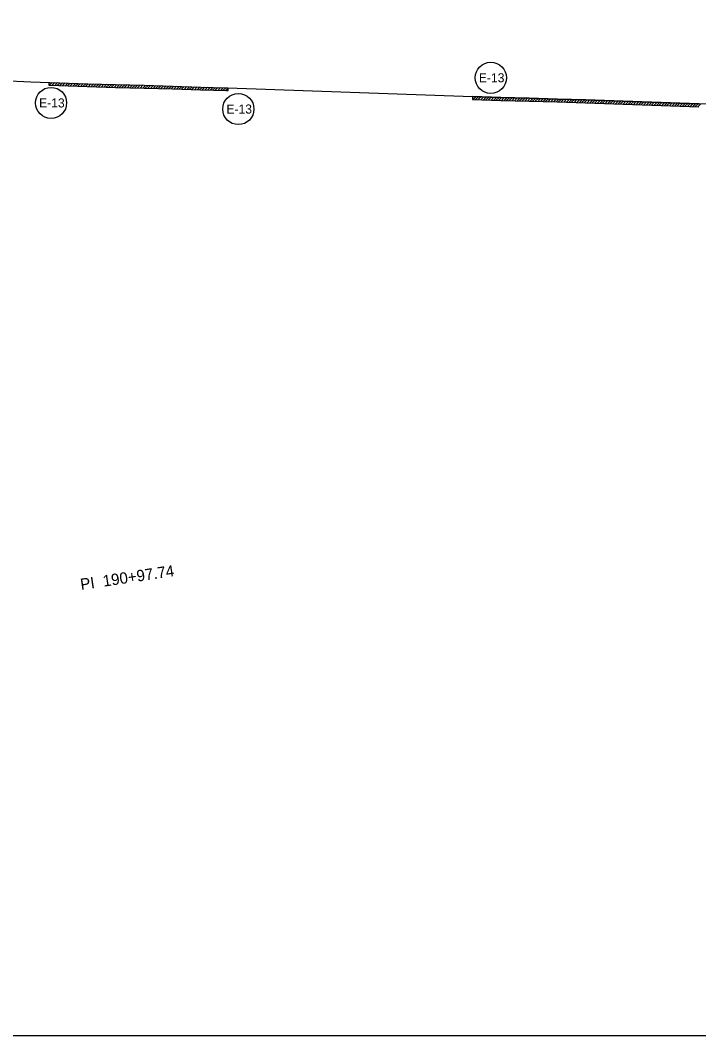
# Model space of a CAD drawing. Extents: x 976877 to 983987, y 1525984 to 1526526.
# Drawn here: x 977846 to 978205, y 1525984 to 1526522 of the extents above; entities that cross this region are included whole.
import ezdxf

# ---------------------------------------------------------------- set-up
doc = ezdxf.new("R2010")
doc.units = 0
for name, color, linetype in [('R_Erosion', 7, 'Continuous'), ('R_Horz Alg Annot', 7, 'Continuous'), ('R_No Plot', 7, 'Continuous')]:
    doc.layers.add(name, color=color, linetype=linetype)

msp = doc.modelspace()

# ---------------------------------------------------------------- linework, layer by layer
at = {"layer": 'R_Erosion'}
for p, q in [((977860.91, 1526489.41), (977860.86, 1526487.91)), ((977860.89, 1526488.9), (977861.38, 1526489.39)), ((977860.91, 1526489.41), (977866.34, 1526489.23)), ((977861.3, 1526487.89), (977862.75, 1526489.35)), ((977862.67, 1526487.85), (977864.12, 1526489.3)), ((977864.04, 1526487.81), (977865.49, 1526489.26)), ((977865.41, 1526487.76), (977866.86, 1526489.21)), ((977866.77, 1526487.71), (977868.22, 1526489.16)), ((977868.13, 1526487.66), (977869.58, 1526489.1)), ((977869.49, 1526487.6), (977870.94, 1526489.05)), ((977870.85, 1526487.55), (977872.3, 1526488.99)), ((977872.21, 1526487.5), (977873.66, 1526488.94)), ((977873.57, 1526487.44), (977875.02, 1526488.88)), ((977874.93, 1526487.39), (977876.38, 1526488.83)), ((977876.29, 1526487.33), (977877.74, 1526488.78)), ((977877.65, 1526487.28), (977879.1, 1526488.72)), ((977879.01, 1526487.22), (977880.46, 1526488.67)), ((977880.37, 1526487.17), (977881.82, 1526488.62)), ((977881.74, 1526487.12), (977883.2, 1526488.58)), ((977883.12, 1526487.09), (977884.58, 1526488.55)), ((977884.5, 1526487.05), (977885.96, 1526488.51)), ((977885.87, 1526487.01), (977887.34, 1526488.48)), ((977887.25, 1526486.98), (977888.71, 1526488.44)), ((977888.63, 1526486.94), (977890.09, 1526488.41)), ((977890.01, 1526486.91), (977891.47, 1526488.37)), ((977891.39, 1526486.87), (977892.85, 1526488.33)), ((977892.77, 1526486.84), (977894.23, 1526488.3)), ((977894.14, 1526486.8), (977895.61, 1526488.26)), ((977895.52, 1526486.76), (977896.99, 1526488.23)), ((977896.33, 1526488.24), (977911.45, 1526487.85)), ((977896.9, 1526486.73), (977898.36, 1526488.19)), ((977898.28, 1526486.69), (977899.74, 1526488.15)), ((977899.66, 1526486.66), (977901.12, 1526488.12)), ((977901.04, 1526486.62), (977902.5, 1526488.08)), ((977902.41, 1526486.58), (977903.88, 1526488.05)), ((977903.79, 1526486.55), (977905.25, 1526488.01)), ((977905.17, 1526486.51), (977906.63, 1526487.97)), ((977906.55, 1526486.48), (977908.01, 1526487.94)), ((977907.93, 1526486.44), (977909.39, 1526487.9)), ((977909.31, 1526486.4), (977910.77, 1526487.87)), ((977910.68, 1526486.37), (977912.14, 1526487.83)), ((977911.45, 1526487.85), (977926.44, 1526487.39)), ((977912.06, 1526486.33), (977913.51, 1526487.78)), ((977913.43, 1526486.29), (977914.89, 1526487.74)), ((977914.8, 1526486.24), (977916.26, 1526487.7)), ((977916.17, 1526486.2), (977917.63, 1526487.66)), ((977917.55, 1526486.16), (977919, 1526487.62)), ((977918.92, 1526486.12), (977920.37, 1526487.57)), ((977920.29, 1526486.08), (977921.75, 1526487.53)), ((977921.66, 1526486.03), (977923.12, 1526487.49)), ((977923.03, 1526485.99), (977924.49, 1526487.45)), ((977924.41, 1526485.95), (977925.86, 1526487.4)), ((977925.78, 1526485.91), (977927.23, 1526487.36)), ((977927.15, 1526485.86), (977928.61, 1526487.32)), ((977928.52, 1526485.82), (977929.98, 1526487.28)), ((977929.89, 1526485.78), (977931.35, 1526487.23)), ((977931.26, 1526485.74), (977932.72, 1526487.19)), ((977932.64, 1526485.69), (977934.09, 1526487.15)), ((977934.01, 1526485.65), (977935.46, 1526487.11)), ((977935.38, 1526485.61), (977936.83, 1526487.06)), ((977936.75, 1526485.56), (977938.21, 1526487.02)), ((977938.12, 1526485.52), (977939.58, 1526486.98)), ((977939.49, 1526485.48), (977940.95, 1526486.93)), ((977940.86, 1526485.44), (977942.32, 1526486.89)), ((977942.24, 1526485.39), (977943.69, 1526486.85)), ((977943.61, 1526485.35), (977945.07, 1526486.81)), ((977944.98, 1526485.31), (977946.44, 1526486.77)), ((977946.36, 1526485.27), (977947.81, 1526486.73)), ((977947.73, 1526485.23), (977949.19, 1526486.69)), ((977949.1, 1526485.19), (977950.56, 1526486.65)), ((977950.48, 1526485.15), (977951.93, 1526486.6)), ((977951.85, 1526485.11), (977953.31, 1526486.56)), ((977953.22, 1526485.07), (977954.68, 1526486.52)), ((977954.59, 1526485.02), (977955.77, 1526486.2)), ((977955.14, 1526486.51), (977955.78, 1526486.49)), ((977955.78, 1526486.49), (977955.74, 1526484.99)), ((978085.55, 1526481.83), (978085.5, 1526480.33)), ((978085.5, 1526480.33), (978100.5, 1526479.86)), ((978085.5, 1526480.33), (978100.5, 1526479.86)), ((978085.54, 1526481.49), (978085.87, 1526481.82)), ((978085.79, 1526480.32), (978087.24, 1526481.78)), ((978087.16, 1526480.28), (978088.61, 1526481.74)), ((978088.53, 1526480.24), (978089.98, 1526481.69)), ((978089.9, 1526480.19), (978091.35, 1526481.65)), ((978091.27, 1526480.15), (978092.72, 1526481.61)), ((978092.64, 1526480.11), (978094.09, 1526481.56)), ((978094.01, 1526480.06), (978095.46, 1526481.52)), ((978095.38, 1526480.02), (978096.84, 1526481.48)), ((978096.75, 1526479.98), (978098.21, 1526481.43)), ((978098.12, 1526479.93), (978099.58, 1526481.39)), ((978099.49, 1526479.89), (978100.95, 1526481.35)), ((978100.87, 1526479.85), (978102.33, 1526481.31)), ((978102.24, 1526479.81), (978103.71, 1526481.28)), ((978103.62, 1526479.78), (978105.08, 1526481.24)), ((978105, 1526479.74), (978106.46, 1526481.2)), ((978106.38, 1526479.7), (978107.84, 1526481.17)), ((978107.76, 1526479.67), (978109.22, 1526481.13)), ((978109.13, 1526479.63), (978110.6, 1526481.09)), ((978110.51, 1526479.6), (978111.97, 1526481.06)), ((978111.89, 1526479.56), (978113.35, 1526481.02)), ((978113.27, 1526479.52), (978114.73, 1526480.99)), ((978114.65, 1526479.49), (978116.11, 1526480.95)), ((978130.52, 1526480.56), (978115.54, 1526480.96)), ((978116.02, 1526479.45), (978117.49, 1526480.91)), ((978117.4, 1526479.41), (978118.86, 1526480.87)), ((978118.78, 1526479.38), (978120.24, 1526480.84)), ((978120.15, 1526479.34), (978121.62, 1526480.8)), ((978121.53, 1526479.3), (978122.99, 1526480.76)), ((978122.91, 1526479.26), (978124.37, 1526480.72)), ((978124.28, 1526479.23), (978125.75, 1526480.69)), ((978125.66, 1526479.19), (978127.12, 1526480.65)), ((978127.04, 1526479.15), (978128.5, 1526480.61)), ((978128.42, 1526479.11), (978129.88, 1526480.57)), ((978129.79, 1526479.08), (978131.25, 1526480.54)), ((978145.51, 1526480.14), (978130.52, 1526480.56)), ((978131.17, 1526479.04), (978132.63, 1526480.5)), ((978132.54, 1526479), (978134, 1526480.46)), ((978133.92, 1526478.96), (978135.38, 1526480.42)), ((978135.3, 1526478.92), (978136.76, 1526480.38)), ((978136.67, 1526478.89), (978138.13, 1526480.35)), ((978138.05, 1526478.85), (978139.51, 1526480.31)), ((978139.42, 1526478.81), (978140.89, 1526480.27)), ((978140.8, 1526478.77), (978142.26, 1526480.23)), ((978100.5, 1526479.86), (978115.5, 1526479.47)), ((978100.5, 1526479.86), (978115.5, 1526479.47)), ((978115.5, 1526479.47), (978130.48, 1526479.06)), ((978115.5, 1526479.47), (978130.48, 1526479.06)), ((978130.48, 1526479.06), (978145.47, 1526478.64)), ((978130.48, 1526479.06), (978145.47, 1526478.64)), ((978142.18, 1526478.73), (978143.64, 1526480.19)), ((978143.55, 1526478.7), (978145.01, 1526480.16)), ((978144.93, 1526478.66), (978146.38, 1526480.11)), ((978145.47, 1526478.64), (978160.45, 1526478.09)), ((978145.47, 1526478.64), (978160.45, 1526478.09)), ((978146.3, 1526478.61), (978147.75, 1526480.06)), ((978147.66, 1526478.56), (978149.11, 1526480.01)), ((978149.03, 1526478.51), (978150.47, 1526479.96)), ((978150.39, 1526478.46), (978151.84, 1526479.91)), ((978151.76, 1526478.41), (978153.2, 1526479.86)), ((978153.12, 1526478.36), (978154.57, 1526479.81)), ((978154.48, 1526478.31), (978155.93, 1526479.76)), ((978155.85, 1526478.26), (978157.3, 1526479.71)), ((978157.21, 1526478.21), (978158.66, 1526479.66)), ((978158.58, 1526478.16), (978160.02, 1526479.61)), ((978159.94, 1526478.11), (978161.39, 1526479.56)), ((978160.46, 1526478.09), (978175.45, 1526477.58)), ((978160.46, 1526478.09), (978175.45, 1526477.58)), ((978161.31, 1526478.06), (978162.76, 1526479.52)), ((978162.68, 1526478.02), (978164.13, 1526479.47)), ((978164.04, 1526477.97), (978165.49, 1526479.42)), ((978165.41, 1526477.93), (978166.86, 1526479.38)), ((978166.78, 1526477.88), (978168.23, 1526479.33)), ((978168.15, 1526477.83), (978169.6, 1526479.28)), ((978169.51, 1526477.79), (978170.97, 1526479.24)), ((978170.88, 1526477.74), (978172.33, 1526479.19)), ((978172.25, 1526477.69), (978173.7, 1526479.15)), ((978173.62, 1526477.65), (978175.07, 1526479.1)), ((978174.99, 1526477.6), (978176.43, 1526479.05)), ((978175.45, 1526477.58), (978190.43, 1526477.02)), ((978175.45, 1526477.58), (978190.43, 1526477.02)), ((978176.35, 1526477.55), (978177.8, 1526479)), ((978177.71, 1526477.5), (978179.16, 1526478.95)), ((978179.08, 1526477.45), (978180.52, 1526478.89)), ((978180.44, 1526477.4), (978181.88, 1526478.84)), ((978181.8, 1526477.35), (978183.25, 1526478.79)), ((978183.16, 1526477.29), (978184.61, 1526478.74)), ((978184.53, 1526477.24), (978185.97, 1526478.69)), ((978185.89, 1526477.19), (978187.34, 1526478.64)), ((978187.25, 1526477.14), (978188.7, 1526478.59)), ((978188.61, 1526477.09), (978190.06, 1526478.53)), ((978189.98, 1526477.04), (978191.42, 1526478.48)), ((978190.43, 1526477.02), (978205.42, 1526476.46)), ((978190.43, 1526477.02), (978205.42, 1526476.46)), ((978191.34, 1526476.99), (978192.79, 1526478.43)), ((978192.7, 1526476.93), (978194.15, 1526478.38)), ((978194.07, 1526476.88), (978195.51, 1526478.33)), ((978195.43, 1526476.83), (978196.88, 1526478.28)), ((978196.79, 1526476.78), (978198.24, 1526478.23)), ((978198.16, 1526476.73), (978199.61, 1526478.18)), ((978199.52, 1526476.68), (978200.97, 1526478.13)), ((978200.89, 1526476.63), (978202.33, 1526478.08)), ((978202.25, 1526476.58), (978203.7, 1526478.03)), ((978203.61, 1526476.53), (978205.06, 1526477.98)), ((978204.98, 1526476.48), (978206.43, 1526477.93))]:
    msp.add_line(p, q, dxfattribs=at)
for points in [[(977860.86, 1526487.91), (977866.29, 1526487.73), (977881.27, 1526487.13)], [(977866.35, 1526489.23), (977881.33, 1526488.63), (977896.33, 1526488.24)], [(977881.29, 1526487.13), (977896.29, 1526486.74), (977911.41, 1526486.35), (977926.4, 1526485.89), (977941.39, 1526485.42)], [(977926.44, 1526487.39), (977941.43, 1526486.92), (977955.13, 1526486.51)], [(977941.39, 1526485.42), (977955.09, 1526485.01), (977955.74, 1526484.99)], [(978115.54, 1526480.96), (978100.54, 1526481.36), (978085.55, 1526481.83)], [(978175.5, 1526479.08), (978160.51, 1526479.59), (978145.52, 1526480.14)], [(978235.56, 1526476.98), (978220.47, 1526477.44), (978205.48, 1526477.96), (978190.49, 1526478.52), (978175.5, 1526479.08)]]:
    msp.add_lwpolyline(points, dxfattribs=at)
for centre in [(978095.21, 1526491.84), (977862.1, 1526478.5), (977961.38, 1526475.27)]:
    msp.add_circle(centre, 8.26, dxfattribs=at)
for centre, start, end in [((977866.29, 1526487.73), 87.7076, 88.151), ((977881.33, 1526488.63), 267.7076, 268.518), ((977896.29, 1526486.74), 88.5, 88.518), ((977911.41, 1526486.35), 88.2388, 88.5), ((977926.4, 1526485.89), 88.2121, 88.2388), ((977955.09, 1526485.01), 88.2294, 88.2858), ((977941.43, 1526486.92), 268.2121, 268.2858), ((978115.5, 1526479.47), 88.4403, 88.4987), ((978130.48, 1526479.06), 88.4147, 88.4403), ((978100.54, 1526481.36), 268.1854, 268.4987), ((978100.54, 1526481.36), 268.1854, 268.4987), ((978145.47, 1526478.64), 87.9025, 88.4147), ((978160.51, 1526479.59), 267.9025, 268.0555), ((978160.51, 1526479.59), 267.9025, 268.0555), ((978175.45, 1526477.58), 87.8375, 88.0555), ((978190.49, 1526478.52), 267.8375, 267.872), ((978205.48, 1526477.96), 267.872, 268.0057), ((978205.48, 1526477.96), 267.872, 268.0057)]:
    msp.add_arc(centre, 1.5, start, end, dxfattribs=at)
at = {"layer": 'R_No Plot'}
msp.add_line((977955.78, 1526486.49), (978085.55, 1526481.83), dxfattribs=at)
for points in [[(980109.47, 1526414.6), (980109.47, 1525984.07), (976876.91, 1525984.07), (976876.91, 1526522.3)], [(977836.36, 1526490.32), (977851.35, 1526489.72), (977866.34, 1526489.23), (977881.33, 1526488.63), (977896.33, 1526488.24), (977911.45, 1526487.85), (977926.44, 1526487.39), (977941.43, 1526486.92), (977955.13, 1526486.51), (977955.78, 1526486.49)], [(978085.55, 1526481.83), (978100.54, 1526481.36), (978115.54, 1526480.96), (978130.52, 1526480.56), (978145.52, 1526480.14), (978160.51, 1526479.59), (978175.5, 1526479.08), (978190.49, 1526478.52), (978205.48, 1526477.96)]]:
    msp.add_lwpolyline(points, dxfattribs=at)
for centre in [(978095.21, 1526491.84), (977862.1, 1526478.5), (977961.38, 1526475.27)]:
    msp.add_circle(centre, 8.26, dxfattribs=at)

# ---------------------------------------------------------------- texts
at = {"layer": 'R_Erosion'}
for p in [(978088.88, 1526489.44), (977855.77, 1526476.1), (977955.05, 1526472.87)]:
    msp.add_text('E-13', height=4.8, dxfattribs=at).set_placement(p)
at = {"layer": 'R_Horz Alg Annot'}
msp.add_text('PI  190+97.74', height=6, rotation=8.4899, dxfattribs=at).set_placement((977878.07, 1526220.28))

doc.saveas('drawing.dxf')
